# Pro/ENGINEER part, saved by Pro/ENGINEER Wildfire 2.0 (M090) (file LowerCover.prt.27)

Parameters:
  PTC_COMMON_NAME = "cover.prt"

Family table entries: PRO_MP_ALT_MASS, ~"x, value(NO_val), PRO_MP_ALT_VOLUME, ~"x, PRO_MP_ALT_AREA, ~"x, PRO_MP_ALT_COGX, ~"x, PRO_MP_ALT_COGY, ~"x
